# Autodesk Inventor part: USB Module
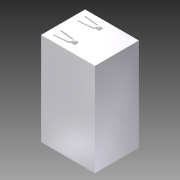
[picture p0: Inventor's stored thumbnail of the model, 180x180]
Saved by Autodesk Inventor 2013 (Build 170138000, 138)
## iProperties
Company: Autodesk Inc.
Created: 2005-11
Part Number: USB Module
Document SubType Name: Modeling
Designer: Autodesk Inc.
Density: 1 g/cm^3
Sheet Metal Rule: Default
Mass: 10.6656 g
Surface Area: 81.1781 cm^2
Volume: 10.6656 cm^3
Material: Allgemein
Title: Personal Computer
Author: Autodesk Inc.
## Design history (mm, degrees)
sketch "Sketch1"
  geometry: L1 (0, 12.6)-(0, -12.6) reference; L2 (-4.4, 0)-(26.4, 0) reference; L3 (0, 9)-(22, 9); L4 (22, 9)-(22, -9); L5 (22, -9)-(0, -9); L6 (0, -9)-(0, 9)
  constraints: 8 end point, 2 parallel, 1 horizontal, 1 perpendicular, 1 point on line, 1 other
  dimensions: "d0" = 18 distance of L3.end L4.end; "d1" = 22 distance of L3.start L3.end
extrude "Extrusion1" new body sketch "Sketch1" distance "d2" = 38; taper "d3" = 0 deg
sketch "Sketch2"
  geometry: L1 (0, 0)-(0, 18) reference; L2 (-7.6, 9)-(45.6, 9) reference; L3 (4, 16.5)-(10, 16.5); L4 (10, 16.5)-(10, 1.5); L5 (10, 1.5)-(4, 1.5); L6 (4, 1.5)-(4, 16.5); L7 (12.5, 16.5)-(18.5, 16.5); L8 (18.5, 16.5)-(18.5, 1.5); L9 (18.5, 1.5)-(12.5, 1.5); L10 (12.5, 1.5)-(12.5, 16.5); L11 (21, 16.5)-(27, 16.5); L12 (27, 16.5)-(27, 1.5); L13 (27, 1.5)-(21, 1.5); L14 (21, 1.5)-(21, 16.5); L15 (29.5, 16.5)-(35.5, 16.5); L16 (35.5, 16.5)-(35.5, 1.5); L17 (35.5, 1.5)-(29.5, 1.5); L18 (29.5, 1.5)-(29.5, 16.5)
  constraints: 32 end point, 8 parallel, 4 collinear, 4 equal length, 4 horizontal, 4 perpendicular, 2 other
  dimensions: "d4" = 4 distance between parallel lines of L1 L6; "d5" = 15 distance of L5.end L3.start; "d6" = 2.5 distance between parallel lines of L10 L4; "d7" = 6 distance of L4.end L5.end; "d9" = 2.5 distance between parallel lines of L8 L14 (= d6); "d44" = 2.5 distance between parallel lines of L12 L18 (= d6)
extrude "Extrusion8" cut sketch "Sketch2" distance "d45" = 15; taper "d46" = 0 deg
sketch "Sketch3"
  geometry: L1 (10, 1.5)-(10, 16.5); L2 (9, 16)-(7.5, 16); L3 (7.5, 16)-(7.5, 2); L4 (7.5, 2)-(9, 2); L5 (9, 2)-(9, 16); L6 (17.5, 16)-(16, 16); L7 (16, 16)-(16, 2); L8 (16, 2)-(17.5, 2); L9 (17.5, 2)-(17.5, 16); L10 (18.5, 1.5)-(18.5, 16.5); L11 (-3.5, 9)-(45.5, 9); L12 (-13.3, 9)-(55.3, 9) reference; L13 (10, 16.5)-(10, 1.5) reference; L14 (18.5, 16.5)-(18.5, 1.5) reference; L15 (21, 16.5)-(21, 1.5) reference; L16 (21, 1.5)-(27, 1.5) reference; L17 (27, 1.5)-(27, 16.5) reference; L18 (27, 16.5)-(21, 16.5) reference; L19 (29.5, 16.5)-(29.5, 1.5) reference; L20 (29.5, 1.5)-(35.5, 1.5) reference; L21 (35.5, 1.5)-(35.5, 16.5) reference; L22 (35.5, 16.5)-(29.5, 16.5) reference; L23 (24.5, 16)-(26, 16); L24 (26, 16)-(26, 2); L25 (26, 2)-(24.5, 2); L26 (24.5, 2)-(24.5, 16); L27 (33, 16)-(34.5, 16); L28 (34.5, 16)-(34.5, 2); L29 (34.5, 2)-(33, 2); L30 (33, 2)-(33, 16)
  constraints: 38 end point, 8 parallel, 7 collinear, 4 equal length, 4 horizontal, 4 perpendicular, 2 other
  dimensions: "d14" = 1.5 distance of L2.start L2.end; "d15" = 1 distance between parallel lines of L1 L5; "d16" = 1 distance between parallel lines of L10 L9 (= d15); "d17" = 14 distance of L2.end L3.end; "d47" = 1 distance between parallel lines of L17 L24 (= d16); "d48" = 1 distance between parallel lines of L21 L28 (= d16)
extrude "Extrusion3" join sketch "Sketch3" distance "d18" = 13; taper "d19" = 0 deg
sketch "Sketch8"
  geometry: L1 (0, -9)-(0, 9) reference; L2 (-4.4, 0)-(26.4, 0) reference; L3 (2.5, 6.75)-(10.5, 6); L4 (10.5, 6)-(10.5, 4); L5 (10.5, 4)-(2.5, 3.25); L6 (2.5, 3.25)-(2.5, 6.75); L7 (2.5, 5)-(4.109, 5)
  constraints: 10 end point, 2 perpendicular, 1 midpoint, 1 parallel, 1 symmetric about line, 1 other
  dimensions: "d49" = 5 distance between parallel lines of L2 L7; "d50" = 2.5 distance between parallel lines of L1 L6; "d51" = 3.5 distance of L5.end L3.start; "d52" = 8 distance between parallel lines of L4 L6; "d53" = 2 distance of L3.end L4.end
extrude "Extrusion9" cut sketch "Sketch8" distance "d54" = 2; taper "d55" = 0 deg
sketch "Sketch9"
  geometry: L1 (2.454, 6.259)-(8.083, 5.732); L2 (8.083, 4.268)-(2.454, 3.741); L3 (2.454, 6.259)-(2.454, 3.741); L4 (8.083, 5.732)-(8.083, 4.268)
  constraints: 8 end point, 1 parallel
extrude "Extrusion10" join sketch "Sketch9" distance "d56" = 0.5; taper "d57" = 0 deg
node "Flange1"
chamfer "Chamfer1" distance "d65" = 0.5; stored, may be unused: second distance "d66" = 2, angle "d67" = 45 deg
mirror "Mirror2"
body "Solid1"
node "Projected Loop2"
node "Projected Loop3"
sketch "Sketch10"
  geometry: L1 through (-0.732, 0) direction (-1, 3.12e-30); L2 (-1.463, 0)-(-1.463, 2); L3 (-1.463, 2)-(0, 2); L4 through (0, 1) direction (-1.02e-16, -1)
  constraints: 6 end point, 1 horizontal, 1 perpendicular, 1 vertical
face "Plate1" dims "d58" = 0.5 (= BendReliefWidth), "d60" = 1 (= MinimumRemnant), "d62" = 2, "d63" = 150 deg, "d64" = 0.5 (= BendRadius), "Thickness" = 0.5
bend "Bend1" dims "d58" = 0.5 (= BendReliefWidth), "d59" = 0.25 (= BendReliefDepth), "d60" = 1 (= MinimumRemnant), "d61" = 0.5 (= BendRadius), "d62" = 2, "d63" = 150 deg, "d64" = 0.5 (= BendRadius), "SeamGap" = 0.01, "Thickness" = 0.5
other parameters: "BendRadius" = 0.5 (= Thickness), "BendReliefWidth" = 0.5 (= Thickness), "BendReliefDepth" = 0.25 (= 0.5 x Thickness), "CornerReliefSize" = 2 (= 4 x Thickness), "MinimumRemnant" = 1 (= 2 x Thickness), "TransitionRadius" = 0.5 (= BendRadius), "JacobiRadiusSize" = 0.5 (= Thickness), "GapSize" = 0.5 (= Thickness)
